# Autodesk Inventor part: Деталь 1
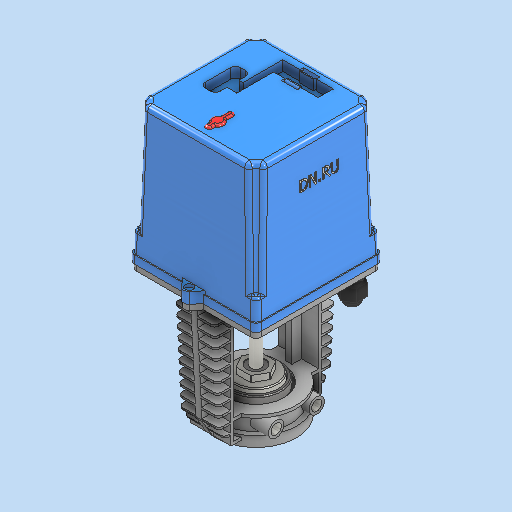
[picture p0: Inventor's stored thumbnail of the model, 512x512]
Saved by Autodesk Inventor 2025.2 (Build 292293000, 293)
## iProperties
Created: 2026-04
Part Number: Деталь 1
Material: Типовые
Document SubType Name: Modeling
Designer: igorr
Density: 1 g/cm^3
Appearance: По умолчанию
Author: igorr
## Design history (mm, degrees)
sketch "Эскиз1"
  geometry: L1 (-62.5, 62.5)-(-62.5, -62.5); L2 (-62.5, -62.5)-(62.5, -62.5); L3 (62.5, -62.5)-(62.5, 62.5); L4 (62.5, 62.5)-(-62.5, 62.5); L5 (-62.5, 62.5)-(62.5, -62.5); L6 (-62.5, -62.5)-(62.5, 62.5); L7 (0, 0)-(0, -71.5); L8 (0, -62.5)-(0, -71.5); L9 (0, 0)-(25.646, 0); L10 (0, -71.5)-(0, -61.5); C1 r 5 at (0, 66.5); 5 further points
  constraints: 20 end point, 6 midpoint, 2 parallel, 2 perpendicular, 2 point on line, 2 vertical, 1 centre point, 1 collinear, 1 symmetric about line, 4 other
  dimensions: "d0" = 125 distance of L1.start L1.end; "d1" = 125 distance of L2.end L1.end; "d2" = 71.5 distance of L7.start L7.end; "d5" = 10 distance of L7.end L10.end
extrude "Выдавливание1" new body sketch "Эскиз1" distance "d3" = 6; taper "d4" = 0 deg
chamfer "Фаска1" distance "d6" = 7.25; stored, may be unused: second distance "d7" = 2, angle "d8" = 45 deg
sketch "Эскиз2"
  geometry: L1 (-62.5, 62.5)-(-62.5, -62.5) reference; L2 (-62.5, -62.5)-(-10.25, -62.5) reference; L3 (-3.841, -69.701)-(-10.25, -62.5) reference; L4 (10.25, -62.5)-(3.841, -69.701) reference; L5 (10.25, -62.5)-(62.5, -62.5) reference; L6 (62.5, -62.5)-(62.5, 62.5) reference; L7 (62.5, 62.5)-(10.25, 62.5) reference; L8 (3.841, 69.701)-(10.25, 62.5) reference; L9 (-10.25, 62.5)-(-3.841, 69.701) reference; L10 (-10.25, 62.5)-(-62.5, 62.5) reference; L11 (61.5, 61.5)-(61.5, -61.5); L12 (61.5, -61.5)-(9.801, -61.5); L13 (9.801, -61.5)-(3.083, -69.049); L14 (-3.083, -69.049)-(-9.801, -61.5); L15 (-9.801, -61.5)-(-61.5, -61.5); L16 (-61.5, -61.5)-(-61.5, 61.5); L17 (-61.5, 61.5)-(-9.801, 61.5); L18 (-9.801, 61.5)-(-3.083, 69.049); L19 (3.083, 69.049)-(9.801, 61.5); L20 (9.801, 61.5)-(61.5, 61.5); A1 r 5 centre (0, -66.5) between (-3.841, -69.701) and (3.841, -69.701) reference; A2 r 5 centre (0, 66.5) between (3.841, 69.701) and (-3.841, 69.701) reference; A3 r 4 centre (0, -66.5) between (-3.083, -69.049) and (3.083, -69.049); A4 r 4 centre (0, 66.5) between (3.083, 69.049) and (-3.083, 69.049); 1 further point
  constraints: 20 end point, 4 point on circle, 2 centre point, 11 other
  dimensions: "d9" = 1 distance between parallel lines of L6 L11
extrude "Выдавливание2" cut sketch "Эскиз2" distance "d10" = 21; taper "d11" = 0 deg
sketch "Эскиз3"
  geometry: L1 (61.5, 61.5)-(9.801, 61.5) reference; L2 (9.801, 61.5)-(3.083, 69.049) reference; L3 (-3.083, 69.049)-(-9.801, 61.5) reference; L4 (-9.801, 61.5)-(-61.5, 61.5) reference; L5 (-61.5, 61.5)-(-61.5, -61.5) reference; L6 (-61.5, -61.5)-(-9.801, -61.5) reference; L7 (-9.801, -61.5)-(-3.083, -69.049) reference; L8 (3.083, -69.049)-(9.801, -61.5) reference; L9 (9.801, -61.5)-(61.5, -61.5) reference; L10 (61.5, -61.5)-(61.5, 61.5) reference; L11 (62.5, -62.5)-(10.25, -62.5); L12 (10.25, -62.5)-(3.841, -69.701); L13 (-3.841, -69.701)-(-10.25, -62.5); L14 (-10.25, -62.5)-(-62.5, -62.5); L15 (-62.5, -62.5)-(-62.5, 62.5); L16 (-62.5, 62.5)-(-10.25, 62.5); L17 (-10.25, 62.5)-(-3.841, 69.701); L18 (3.841, 69.701)-(10.25, 62.5); L19 (10.25, 62.5)-(62.5, 62.5); L20 (62.5, 62.5)-(62.5, -62.5); A1 r 4 centre (0, 66.5) between (3.083, 69.049) and (-3.083, 69.049) reference; A2 r 4 centre (0, -66.5) between (-3.083, -69.049) and (3.083, -69.049) reference; A3 r 5 centre (0, -66.5) between (-3.841, -69.701) and (3.841, -69.701); A4 r 5 centre (0, 66.5) between (3.841, 69.701) and (-3.841, 69.701); 1 further point
  constraints: 20 end point, 4 point on circle, 2 centre point, 11 other
  dimensions: "d12" = 1 distance between parallel lines of L9 L11
extrude "Выдавливание3" join sketch "Эскиз3" distance "d13" = 8; taper "d14" = 0 deg
sketch "Эскиз4"
  geometry: L1 (61.5, -61.5)-(61.5, 61.5); L2 (61.5, 61.5)-(-61.5, 61.5); L3 (-61.5, 61.5)-(-61.5, -61.5); L4 (-61.5, -61.5)-(61.5, -61.5); L5 (61.5, -61.5)-(-61.5, 61.5); L6 (61.5, 61.5)-(-61.5, -61.5); 1 further point
  constraints: 12 end point, 2 midpoint, 2 parallel, 1 perpendicular, 1 vertical
  dimensions: "d15" = 123 distance of L1.start L1.end; "d16" = 123 distance of L2.end L1.end
extrude "Выдавливание4" join sketch "Эскиз4" distance "d17" = 130; taper "d18" = -1 deg
sketch "Эскиз5"
  geometry: L1 (61.5, 61.5)-(61.5, -61.5) reference; L2 (61.5, -61.5)-(-61.5, -61.5) reference; L3 (-61.5, -61.5)-(-61.5, 61.5) reference; L4 (-61.5, 61.5)-(61.5, 61.5) reference; L5 (-3.841, 69.701)-(-10.25, 62.5) reference; L6 (-10.25, 62.5)-(-62.5, 62.5) reference; L7 (-62.5, 62.5)-(-62.5, -62.5) reference; L8 (-62.5, -62.5)-(-10.25, -62.5) reference; L9 (-10.25, -62.5)-(-3.841, -69.701) reference; L10 (3.841, -69.701)-(10.25, -62.5) reference; L11 (10.25, -62.5)-(62.5, -62.5) reference; L12 (62.5, -62.5)-(62.5, 62.5) reference; L13 (62.5, 62.5)-(10.25, 62.5) reference; L14 (10.25, 62.5)-(3.841, 69.701) reference; L15 (10.25, 62.5)-(14.397, 57.84); L16 (14.397, 57.84)-(-14.397, 57.84); L17 (-14.397, 57.84)-(-10.25, 62.5); L18 (62.5, 0)-(81.182, 0); L19 (10.25, -62.5)-(3.841, -69.701); L20 (-3.841, -69.701)-(-10.25, -62.5); L21 (14.397, -57.84)-(-14.397, -57.84); L22 (10.25, -62.5)-(14.397, -57.84); L23 (-14.397, -57.84)-(-10.25, -62.5); C1 r 4 at (0, 66.101); C2 r 4 at (0, -66.101); A1 r 5 centre (0, -66.5) between (-3.841, -69.701) and (3.841, -69.701) reference; A2 r 5 centre (0, 66.5) between (3.841, 69.701) and (-3.841, 69.701) reference; A3 r 5 centre (0, -66.5) between (-3.841, -69.701) and (3.841, -69.701); 1 further point
  constraints: 18 end point, 4 symmetric about line, 3 centre point, 2 horizontal, 2 point on circle, 2 point on line, 1 collinear, 1 midpoint, 2 other
  dimensions: "d19" = 8 diameter of C1
extrude "Выдавливание5" join sketch "Эскиз5" distance "d20" = 3; taper "d21" = 0 deg
sketch "Эскиз6"
  geometry: L1 (-59.231, 59.231)-(59.231, 59.231) reference; C1 r 7.5 at (59.231, 59.231); C2 r 7.5 at (-59.231, 59.231); C3 r 7.5 at (-59.231, -59.231); C4 r 7.5 at (59.231, -59.231); 1 further point
  constraints: 4 centre point, 9 other
  dimensions: "d22" = 15 diameter of C1; "d25" = 360 deg dimension on point (0, 0) L1.end (derived)
extrude "Выдавливание6" cut sketch "Эскиз6" distance "d27" = 110; taper "d28" = -2 deg
sketch "Эскиз7"
  geometry: L1 (-21.282, 47.681)-(28.718, 47.681); L2 (28.718, 47.681)-(28.718, 32.681); L3 (28.718, 32.681)-(-21.282, 32.681); L4 (-21.282, 32.681)-(-21.282, 47.681); L5 (-21.282, 47.681)-(28.718, 32.681); L6 (28.718, 47.681)-(-21.282, 32.681); L7 (-40.282, 15)-(-40.282, -10); L8 (-35.282, -15)-(-30.282, -15); L9 (-25.282, -10)-(-25.282, 15); L10 (-30.282, 20)-(-35.282, 20); L11 (-40.282, 20)-(-25.282, -15); L12 (-40.282, -15)-(-25.282, 20); L13 (-35.282, 8.5)-(-15.282, 8.5); L14 (-15.282, 8.5)-(-15.282, -3.5); L15 (-15.282, -3.5)-(-35.282, -3.5); L16 (-35.282, -3.5)-(-35.282, 8.5); L17 (-35.282, 8.5)-(-15.282, -3.5); L18 (-15.282, 8.5)-(-35.282, -3.5); L19 (-15.282, -3.5)-(-21.282, -3.5); L20 (-21.282, -3.5)-(-21.282, 50.128); L21 (-21.282, 50.128)-(-15.282, 50.128); L22 (-15.282, 50.128)-(-15.282, -3.5); L23 (-4.282, 51.181)-(-4.282, 29.181); L24 (-4.282, 29.181)-(11.718, 29.181); L25 (11.718, 29.181)-(11.718, 51.181); L26 (11.718, 51.181)-(-4.282, 51.181); L27 (-4.282, 51.181)-(11.718, 29.181); L28 (-4.282, 29.181)-(11.718, 51.181); A1 r 5 centre (-30.282, 15) between (-25.282, 15) and (-30.282, 20); A2 r 5 centre (-30.282, -10) between (-30.282, -15) and (-25.282, -10); A3 r 5 centre (-35.282, -10) between (-40.282, -10) and (-35.282, -15); A4 r 5 centre (-35.282, 15) between (-35.282, 20) and (-40.282, 15); 14 further points
  constraints: 56 end point, 10 parallel, 9 midpoint, 9 point on line, 8 point on circle, 8 tangent, 5 perpendicular, 4 centre point, 3 equal radius, 2 horizontal, 2 vertical, 1 collinear
  dimensions: "d29" = 50 distance of L1.start L1.end; "d30" = 15 distance of L1.end L2.end; "d31" = 35 distance of L11.start L12.start; "d32" = 15 distance of L11.end L12.start; "d33" = 20 distance of L13.start L13.end; "d34" = 12 distance of L13.end L14.end; "d35" = 6 distance of L14.end L19.end; "d36" = 22 distance of L23.start L23.end; "d37" = 16 distance of L24.end L23.end; "d38" = 5 radius of A1
extrude "Выдавливание7" cut sketch "Эскиз7" distance "d39" = 10; taper "d40" = 0 deg
sketch "Эскиз8"
  geometry: L1 (0, -46.285)-(0, -25.359); L2 (-15.282, 32.681)-(-15.282, -3.5) reference; L3 (3, -46.285)-(3, -25.359); L4 (-3, -25.359)-(-3, -46.285); C1 r 6 at (0, -38.032); A1 r 3 centre (0, -46.285) between (-3, -46.285) and (3, -46.285); A2 r 3 centre (0, -25.359) between (3, -25.359) and (-3, -25.359); 6 further points
  constraints: 8 end point, 4 point on circle, 4 tangent, 3 centre point, 2 parallel, 1 midpoint
  dimensions: "d41" = 12 diameter of C1; "d42" = 6 diameter of A2
extrude "Выдавливание8" join sketch "Эскиз8" distance "d43" = 2; taper "d44" = 0 deg
sketch "Эскиз9"
  geometry: L1 (-4.282, 51.181)-(11.718, 51.181) reference; L2 (11.718, 29.181)-(-4.282, 29.181) reference; L3 (11.718, 51.181)-(-4.282, 29.181); L4 (-3.282, 49.181)-(-3.282, 31.181); L5 (-3.282, 31.181)-(10.718, 31.181); L6 (10.718, 31.181)-(10.718, 49.181); L7 (10.718, 49.181)-(-3.282, 49.181); L8 (-3.282, 49.181)-(10.718, 31.181); L9 (-3.282, 31.181)-(10.718, 49.181); L10 (-3.282, 46.181)-(10.718, 46.181); L11 (10.718, 46.181)-(10.718, 34.181); L12 (10.718, 34.181)-(-3.282, 34.181); L13 (-3.282, 34.181)-(-3.282, 46.181); L14 (-3.282, 46.181)-(10.718, 34.181); L15 (10.718, 46.181)-(-3.282, 34.181); 6 further points
  constraints: 26 end point, 5 midpoint, 4 parallel, 2 perpendicular, 1 vertical
  dimensions: "d45" = 18 distance of L4.start L4.end; "d46" = 14 distance of L5.end L4.end; "d47" = 12 distance of L10.end L11.end
extrude "Выдавливание9" join sketch "Эскиз9" stored distance "d48" = 2; taper "d49" = 0 deg
sketch "Эскиз11"
  geometry: C1 r 22.5 at (0, 0); C2 r 25 at (0, 0); 1 further point
  constraints: 2 centre point, 1 coincident
  dimensions: "d50" = 45 diameter of C1; "d51" = 2.5 radial gap between concentric circles of C1 C2
extrude "Выдавливание10" cut sketch "Эскиз11" distance "d52" = 10; taper "d53" = 0 deg
sketch "Эскиз12"
  geometry: L1 (3, -61.5)-(3, 61.5); L2 (3, 61.5)-(-3, 61.5); L3 (-3, 61.5)-(-3, -61.5); L4 (-3, -61.5)-(3, -61.5); L5 (3, -61.5)-(-3, 61.5); L6 (3, 61.5)-(-3, -61.5); L7 (-9.801, 61.5)-(-61.5, 61.5) reference; L8 (3, -32.5)-(-3, -32.5); L9 (-3, -32.5)-(-3, 32.5); L10 (-3, 32.5)-(3, 32.5); L11 (3, 32.5)-(3, -32.5); L12 (3, -32.5)-(-3, 32.5); L13 (-3, -32.5)-(3, 32.5); L14 (20, -45.032)-(-20, -45.032); L15 (-20, -45.032)-(-20, -42.032); L16 (-20, -42.032)-(20, -42.032); L17 (20, -42.032)-(20, -45.032); L18 (20, -45.032)-(-20, -42.032); L19 (-20, -45.032)-(20, -42.032); L20 (-3, 0)-(-7.639, 0); L21 (20, 42.032)-(20, 45.032); L22 (-20, 42.032)-(20, 42.032); L23 (-20, 45.032)-(20, 42.032); L24 (20, 45.032)-(-20, 42.032); L25 (20, 45.032)-(-20, 45.032); L26 (-20, 45.032)-(-20, 42.032); 15 further points
  constraints: 50 end point, 9 midpoint, 7 parallel, 5 symmetric about line, 3 perpendicular, 2 collinear, 1 horizontal
  dimensions: "d54" = 6 distance of L2.end L1.end; "d55" = 65 distance of L8.end L9.end; "d58" = 40 distance of L14.start L14.end; "d59" = 3 distance of L14.end L15.end
extrude "Выдавливание11" join sketch "Эскиз12" distance "d56" = 120; taper "d57" = 0 deg
sketch "Эскиз13"
  geometry: C1 r 25 at (0, 0) reference; C2 r 40 at (0, 0); 1 further point
  constraints: 1 centre point, 1 coincident
  dimensions: "d60" = 80 diameter of C2
extrude "Выдавливание12" join sketch "Эскиз13" stored distance "d61" = 10; taper "d63" = 0 deg; dims "d62" = 2, "d64" = 0
sketch "Эскиз14"
  geometry: C1 r 40 at (0, 0) reference; C2 r 35 at (0, 0); 1 further point
  constraints: 1 centre point, 1 coincident
  dimensions: "d65" = 70 diameter of C2
extrude "Выдавливание13" join sketch "Эскиз14" distance "d66" = 15; taper "d67" = 0 deg
sketch "Эскиз15"
  geometry: L1 (-20, 42.032)-(-20, -42.032); L2 (-20, -42.032)-(20, -42.032); L3 (20, -42.032)-(20, 42.032); L4 (20, 42.032)-(-20, 42.032); L5 (-20, 42.032)-(20, -42.032); L6 (-20, -42.032)-(20, 42.032); L7 (3, -42.032)-(20, -42.032) reference; C1 r 40 at (0, 0); C2 r 27.5 at (0, 0); A1 r 40 centre (0, 0) between (3, -39.887) and (3, 39.887) reference; 5 further points
  constraints: 12 end point, 2 centre point, 2 coincident, 2 midpoint, 2 parallel, 1 collinear, 1 concentric, 1 perpendicular, 1 vertical
  dimensions: "d68" = 40 distance of L2.end L1.end; "d69" = 55 diameter of C2
extrude "Выдавливание14" join sketch "Эскиз15" distance "d70" = 3; taper "d71" = 0 deg
sketch "Эскиз16"
  geometry: L1 (20, 42.032)-(20, -42.032); L2 (20, -42.032)-(-20, -42.032); L3 (-20, -42.032)-(-20, 42.032); L4 (-20, 42.032)-(20, 42.032); L5 (20, 42.032)-(-20, -42.032); L6 (20, -42.032)-(-20, 42.032); A1 r 40 centre (0, 0) between (-20, 34.641) and (-20, -34.641) reference; 1 further point
  constraints: 12 end point, 2 midpoint, 2 parallel, 1 perpendicular, 1 vertical
extrude "Выдавливание15" join sketch "Эскиз16" distance "d72" = 3; taper "d73" = 0 deg
sketch "Эскиз17"
  geometry: L1 (0, -61.5)-(-120, -61.5) reference; L2 (0, -61.5)-(-9, -61.5); L3 (0, -42.032)-(-97, -42.032) reference; L4 (-9, -61.5)-(-9, -42.032); L5 (-9, -42.032)-(-11, -42.032); L6 (-11, -42.032)-(-11, -61.5); L7 (-11, -61.5)-(-9, -61.5); 3 further points
  constraints: 10 end point, 2 parallel, 2 point on line, 1 perpendicular, 1 vertical
  dimensions: "d74" = 9 distance of L1.start L2.end; "d75" = 2 distance of L5.end L4.end
extrude "Выдавливание16" join sketch "Эскиз17" stored distance "d76" = 40; taper "d77" = 0 deg
pattern_linear "Прямоуг.массив1"
mirror "Зеркальное отражение1"
sketch "Эскиз18"
  geometry: L1 (10.391, 0)-(0, 0) reference; L2 (0, 0)-(-11.293, 18.805); L3 (-16.468, 120)-(-16.468, 111) reference; L4 (-11.293, 18.805)-(-16.468, 120); L5 (0, 0)-(-16.468, 0) reference; L6 (-16.468, 120)-(-16.468, 0); L7 (-16.468, 0)-(0, 0); L8 (45.032, 120)-(45.032, 160.583); L9 (79.673, 0)-(90.064, 0); L10 (90.064, 0)-(101.357, 18.805); L11 (106.532, 120)-(106.532, 111); L12 (101.357, 18.805)-(106.532, 120); L13 (90.064, 0)-(106.532, 0); L14 (106.532, 120)-(106.532, 0); L15 (106.532, 0)-(90.064, 0); 2 further points
  constraints: 24 end point, 6 symmetric about line, 2 perpendicular, 1 vertical
extrude "Выдавливание17" cut sketch "Эскиз18" distance "d81" = 40; taper "d82" = 0 deg
sketch "Эскиз19"
  geometry: C1 r 27.5 at (0, 0) reference; C2 r 21 at (0, 0); 1 further point
  constraints: 1 centre point, 1 coincident
  dimensions: "d83" = 42 diameter of C2
extrude "Выдавливание18" join sketch "Эскиз19" distance "d84" = 12; taper "d85" = 0 deg
sketch "Эскиз20"
  geometry: L1 (14.383, 0)-(7.192, -12.456); L2 (7.192, -12.456)-(-7.192, -12.456); L3 (-7.192, -12.456)-(-14.383, 0); L4 (-14.383, 0)-(-7.192, 12.456); L5 (-7.192, 12.456)-(7.192, 12.456); L6 (7.192, 12.456)-(14.383, 0); 2 further points
  constraints: 12 end point, 1 coincident, 13 other
extrude "Выдавливание19" join sketch "Эскиз20" distance "d86" = 6; taper "d87" = 0 deg
sketch "Эскиз21"
  geometry: C1 r 9 at (0, 0); 1 further point
  constraints: 1 centre point, 1 coincident
  dimensions: "d88" = 18 diameter of C1
extrude "Выдавливание20" cut sketch "Эскиз21" distance "d89" = 1; taper "d90" = 0 deg
sketch "Эскиз22"
  geometry: C1 r 5 at (0, 0); 1 further point
  constraints: 1 centre point, 1 coincident
  dimensions: "d91" = 10 diameter of C1
extrude "Выдавливание21" join sketch "Эскиз22" distance "d92" = 48; taper "d93" = 0 deg
sketch "Эскиз23"
  geometry: C1 r 6.5 at (0, 0); 1 further point
  constraints: 1 centre point, 1 coincident
  dimensions: "d94" = 13 diameter of C1
extrude "Выдавливание22" join sketch "Эскиз23" distance "d95" = 15; taper "d96" = 0 deg
sketch "Эскиз24"
  geometry: L1 (-12.923, -15)-(-29.672, -15); L2 (-29.672, -15)-(-29.672, 15); L3 (-29.672, 15)-(-12.923, 15); L4 (-12.923, 15)-(-12.923, -15); L5 (-20, -6.5)-(-20, 6.5) reference; L6 (-12.923, -15)-(-29.672, 15); L7 (-29.672, -15)-(-12.923, 15); 2 further points
  constraints: 12 end point, 3 parallel, 2 midpoint, 1 perpendicular
  dimensions: "d97" = 30 distance of L1.end L2.end
extrude "Выдавливание23" join sketch "Эскиз24" stored distance "d98" = 8; taper "d99" = 0 deg
sketch "Эскиз25"
  geometry: L1 (-0.5, 21)-(8.5, 21); L2 (8.5, 21)-(8.5, 9); L3 (8.5, 9)-(-0.5, 9); L4 (-0.5, 9)-(-0.5, 21); L5 (-0.5, 21)-(8.5, 9); L6 (8.5, 21)-(-0.5, 9); A1 r 6.5 centre (4, 15) between (0, 20.123) and (0, 9.877) reference; 1 further point
  constraints: 12 end point, 2 midpoint, 2 parallel, 1 horizontal, 1 perpendicular
  dimensions: "d100" = 9 distance of L1.start L1.end; "d101" = 12 distance of L1.end L2.end
extrude "Выдавливание24" join sketch "Эскиз25" distance "d102" = 15; taper "d103" = 0 deg
sketch "Эскиз26"
  geometry: L1 (-1, -2.664)-(13, -2.664); L2 (13, -2.664)-(13, 4.336); L3 (6, 11.336)-(6, 11.336); L4 (-1, 4.336)-(-1, -2.664); L5 (-1, -2.664)-(13, 11.336); L6 (13, -2.664)-(-1, 11.336); A1 r 7 centre (6, 4.336) between (6, 11.336) and (-1, 4.336); A2 r 7 centre (6, 4.336) between (13, 4.336) and (6, 11.336); 3 further points
  constraints: 12 end point, 4 point on circle, 4 point on line, 4 tangent, 2 centre point, 2 midpoint, 2 parallel, 1 concentric, 1 horizontal, 1 perpendicular
  dimensions: "d104" = 14 distance of L1.start L1.end; "d105" = 14 distance of L5.end L1.end; "d106" = 7 radius of A1
extrude "Выдавливание25" join sketch "Эскиз26" distance "d107" = 2; taper "d108" = 0 deg
sketch "Эскиз27"
  geometry: L1 (-7, -15.587)-(7, -15.587) reference; L2 (-7, -15.587)-(7, -15.587); L3 (7, -15.587)-(7, -12.923); L4 (7, -12.923)-(-7, -12.923); L5 (-7, -12.923)-(-7, -15.587); 1 further point
  constraints: 8 end point, 3 equal length, 1 perpendicular
extrude "Выдавливание26" join sketch "Эскиз27" stored distance "d109" = 2; taper "d110" = 0 deg
mirror "Зеркальное отражение2"
sketch "Эскиз31"
  geometry: L1 (-100, -34.871)-(-115, -34.871) reference; L2 (-107.5, -34.871)-(-107.5, 34.871); L3 (-100, 34.871)-(-115, 34.871) reference; C1 r 7.5 at (-107.5, 0); C2 r 5 at (-107.5, 0); 1 further point
  constraints: 3 midpoint, 2 centre point, 2 end point, 1 coincident
  dimensions: "d117" = 10 diameter of C2
extrude "Выдавливание30" join sketch "Эскиз31" distance "d118" = 40; taper "d119" = 0 deg
sketch "Эскиз32"
  geometry: L1 (-100, 34.871)-(-115, 34.871) reference; L2 (-107.5, 34.871)-(-107.5, -34.871); L3 (-115, -34.871)-(-100, -34.871) reference; L4 (-100, 0)-(-100, 34.871) reference; L5 (-97, 27.5)-(-97, -27.5) reference; L6 (-97, 0)-(-91.595, 0); C1 r 7.5 at (-107.5, 20.02); C2 r 5 at (-107.5, 20.02); C3 r 7.5 at (-107.5, -20.02); C4 r 5 at (-107.5, -20.02); 1 further point
  constraints: 4 centre point, 4 end point, 4 midpoint, 2 coincident, 2 symmetric about line, 1 horizontal, 1 point on line, 1 tangent, 2 other
  dimensions: "d120" = 10 diameter of C2
extrude "Выдавливание31" join sketch "Эскиз32" distance "d121" = 40; taper "d122" = 0 deg
sketch "Эскиз33"
  geometry: L1 (58.359, -47.515)-(52.809, -56.952); L2 (52.809, -56.952)-(41.862, -56.863); L3 (41.862, -56.863)-(36.465, -47.338); L4 (36.465, -47.338)-(42.015, -37.902); L5 (42.015, -37.902)-(52.963, -37.991); L6 (52.963, -37.991)-(58.359, -47.515); L7 (45.512, 27.742)-(45.512, 7.03); L8 (45.512, 7.03)-(57.512, 7.03); L9 (57.512, 7.03)-(57.512, 27.742); L10 (57.512, 27.742)-(45.512, 27.742); L11 (45.512, 27.742)-(57.512, 7.03); L12 (45.512, 7.03)-(57.512, 27.742); C1 r 10 at (47.412, 43.457); 3 further points
  constraints: 24 end point, 2 midpoint, 2 parallel, 1 centre point, 1 perpendicular, 1 vertical, 13 other
  dimensions: "d123" = 20 diameter of C1; "d124" = 12 distance of L8.end L7.end
extrude "Выдавливание32" join sketch "Эскиз33" distance "d125" = 3; taper "d126" = 0 deg
node "Непосредственное редактирование1"
sketch "Эскиз34"
  geometry: L1 (10.948, 0)-(0, 0) reference; L2 (10.948, -18.962)-(0, -18.962) reference; L3 (10.948, 0)-(0, -18.962); C1 r 7.5 at (5.474, -9.481); 1 further point
  constraints: 2 end point, 1 centre point, 1 midpoint
  dimensions: "d130" = 15 diameter of C1
extrude "Выдавливание33" join sketch "Эскиз34" distance "d131" = 5; taper "d132" = 0 deg
sketch "Эскиз35"
  geometry: L1 (9.679, -5.536)-(0.046, -11.15); L2 (0.046, -11.15)-(-9.634, -5.615); L3 (-9.634, -5.615)-(-9.679, 5.536); L4 (-9.679, 5.536)-(-0.046, 11.15); L5 (-0.046, 11.15)-(9.634, 5.615); L6 (9.634, 5.615)-(9.679, -5.536); C1 r 7.5 at (0, 0) reference; 2 further points
  constraints: 12 end point, 1 coincident, 13 other
extrude "Выдавливание34" join sketch "Эскиз35" distance "d133" = 12; taper "d134" = 0 deg
sketch "Эскиз36"
  geometry: C1 r 9 at (0, 0); C2 r 7.5 at (0, 0) reference; C3 r 4 at (0, 0); 1 further point
  constraints: 2 centre point, 1 coincident
  dimensions: "d135" = 18 diameter of C1; "d136" = 8 diameter of C3
extrude "Выдавливание35" join sketch "Эскиз36" distance "d137" = 8; taper "d138" = 0 deg
sketch "Эскиз37"
  geometry: L1 (43.658, 99.007)-(55.919, 99.007); L2 (55.919, 99.007)-(55.919, 95.895); L3 (55.919, 95.895)-(43.658, 95.895); L4 (43.658, 95.895)-(43.658, 99.007); 1 further point
  constraints: 2 other
feature "Рельеф1" sketch "Эскиз37" dims "d6" = 7.25, "d139" = 0.5, "d140" = 0
fillet "Сопряжение1" dims "d145" = 5
fillet "Сопряжение2" dims "d146" = 2
fillet "Сопряжение3" dims "d147" = 4
fillet "Сопряжение4" dims "d148" = 2
sketch "Эскиз40"
  geometry: C1 r 2.5 at (-8.587, 0); A1 r 7 centre (-8.587, 0) between (-8.587, -7) and (-8.587, 7) reference; 1 further point
  constraints: 1 centre point, 1 coincident
  dimensions: "d149" = 5 diameter of C1
extrude "Выдавливание38" join sketch "Эскиз40" stored distance "d150" = 25; taper "d151" = 0 deg
sketch "Эскиз41"
  geometry: L1 (5, -35)-(-5, -35) reference; L2 (0, -35)-(0, -34.078); C1 r 3 at (-10.058, -24.967); C2 r 3 at (10.058, -24.967); 1 further point
  constraints: 2 centre point, 2 end point, 1 midpoint, 1 symmetric about line, 1 vertical, 1 other
  dimensions: "d152" = 6 diameter of C1
extrude "Выдавливание39" cut sketch "Эскиз41" stored distance "d153" = 25; taper "d154" = 0 deg
sketch "Эскиз42"
  geometry: C1 r 27.5 at (0, 0) reference; 1 further point
extrude "Выдавливание40" cut sketch "Эскиз42" distance "d155" = 3; taper "d156" = 0 deg
chamfer "Фаска2" distance "d161" = 1; stored, may be unused: second distance "d162" = 2, angle "d163" = 45 deg
sketch "Эскиз44"
  geometry: C1 r 21 at (0, 0) reference; C2 r 25 at (0, 0); C3 r 22 at (0, 0); 1 further point
  constraints: 2 centre point
  dimensions: "d164" = 4 radial gap between concentric circles of C1 C2; "d165" = 1 radial gap between concentric circles of C1 C3
extrude "Выдавливание42" join sketch "Эскиз44" distance "d166" = 8; taper "d167" = 0 deg
fillet "Сопряжение6" dims "d168" = 1
fillet "Сопряжение7" dims "d169" = 1
node "Твердое тело1"
node "Спроецированная петля1"
node "Спроецированная петля2"
node "Спроецированная петля3"
node "Эскиз — круговой массив1" dims "d25" = 360 deg (derived)
feature "Перенос1" dims "d129" = 2
other parameters: "d127" = 0, "d128" = 0
